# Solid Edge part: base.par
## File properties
Author: f_grande
Template: Normal.par
Last saved by: f_grande
Revision: 2
Application: Solid Edge
Material: Plexiglas opalino
Stile della faccia: Bianco (vetro)
Stile di riempimento: ANSI34(Plastica)
Stile virtuale: Marroncino (lucido)
Coef. of Thermal Exp: 0.0
Thermal Conductivity: 1.5
Specific Heat: 0.0
Modulus of Elasticity: 2757902.8
Poisson's Ratio: 0.4
Yield Stress: 6894757.0
Ultimate Stress: 0.0
Elongation: 0.0
Tipo di contenuto documento: 0
Densità: 1385,000 kg/m^3
Precisione: 0,990
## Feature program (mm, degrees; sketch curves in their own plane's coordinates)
sketch for "unnamed Protrusion 1" plane through (0, 0, 0) normal (0, 0, 1) x-axis (1, 0, 0)
  line (-24.5, 24.5) -> (24.5, 24.5)
  line (24.5, 24.5) -> (24.5, -24.5)
  line (24.5, -24.5) -> (-24.5, -24.5)
  line (-24.5, -24.5) -> (-24.5, 24.5)
  dimension (linear) = 24.5
  dimension (linear) = 24.5
extrude "unnamed Protrusion 1" add finite 1 along +normal
fillet "Rotondo_1" radius 3
sketch for "ExtrudedCutout_1" #1 plane through (0, 0, 1) normal (0, 0, 1) x-axis (1, 0, 0)
  circle centre (-24.5, 0) radius 2.5
sketch for "ExtrudedCutout_1" #2 plane through (0, 0, 1) normal (0, 0, 1) x-axis (1, 0, 0)
  circle centre (24.5, 0) radius 2.5
extrude "ExtrudedCutout_1" cut finite 135 along -normal
sketch for "ExtrudedCutout_2" plane through (0, 0, 1) normal (0, 0, 1) x-axis (1, 0, 0)
  line (-10.5, 24.5) -> (-10.5, 22.5)
  line (-10.5, 22.5) -> (-9.5, 22.5)
  line (-9.5, 22.5) -> (-9.5, 24.5)
  line (-9.5, 24.5) -> (-10.5, 24.5)
extrude "ExtrudedCutout_2" cut finite 135 along -normal
sketch for "ExtrudedCutout_3" plane through (0, 0, 1) normal (0, 0, 1) x-axis (1, 0, 0)
  line (9.5, 24.5) -> (9.5, 22.5)
  line (9.5, 22.5) -> (10.5, 22.5)
  line (10.5, 22.5) -> (10.5, 24.5)
  line (10.5, 24.5) -> (9.5, 24.5)
  dimension (linear) = 9.5
  dimension (linear) = 10.5
extrude "ExtrudedCutout_3" cut finite 135 along -normal
sketch for "ExtrudedCutout_4" #1 plane through (0, 0, 1) normal (0, 0, 1) x-axis (1, 0, 0)
  line (-9.5, -24.5) -> (-9.5, -22.5)
  line (-9.5, -22.5) -> (-10.5, -22.5)
  line (-10.5, -22.5) -> (-10.5, -24.5)
  line (-10.5, -24.5) -> (-9.5, -24.5)
sketch for "ExtrudedCutout_4" #2 plane through (0, 0, 1) normal (0, 0, 1) x-axis (1, 0, 0)
  line (10.5, -24.5) -> (10.5, -22.5)
  line (10.5, -22.5) -> (9.5, -22.5)
  line (9.5, -22.5) -> (9.5, -24.5)
  line (9.5, -24.5) -> (10.5, -24.5)
extrude "ExtrudedCutout_4" cut finite 135 along -normal
sketch for "ExtrudedCutout_5" #1 plane through (0, 0, 1) normal (0, 0, 1) x-axis (1, 0, 0)
  line (-24.5, -9.5) -> (-22.5, -9.5)
  line (-22.5, -9.5) -> (-22.5, -10.5)
  line (-22.5, -10.5) -> (-24.5, -10.5)
  line (-24.5, -10.5) -> (-24.5, -9.5)
sketch for "ExtrudedCutout_5" #2 plane through (0, 0, 1) normal (0, 0, 1) x-axis (1, 0, 0)
  line (24.5, 10.5) -> (22.5, 10.5)
  line (22.5, 10.5) -> (22.5, 9.5)
  line (22.5, 9.5) -> (24.5, 9.5)
  line (24.5, 9.5) -> (24.5, 10.5)
sketch for "ExtrudedCutout_5" #3 plane through (0, 0, 1) normal (0, 0, 1) x-axis (1, 0, 0)
  line (24.5, -10.5) -> (22.5, -10.5)
  line (22.5, -10.5) -> (22.5, -9.5)
  line (22.5, -9.5) -> (24.5, -9.5)
  line (24.5, -9.5) -> (24.5, -10.5)
sketch for "ExtrudedCutout_5" #4 plane through (0, 0, 1) normal (0, 0, 1) x-axis (1, 0, 0)
  line (-24.5, 10.5) -> (-24.5, 11.5)
  line (-24.5, 11.5) -> (-22.5, 11.5)
  line (-22.5, 11.5) -> (-22.5, 10.5)
  line (-22.5, 10.5) -> (-24.5, 10.5)
  dimension (linear) = 22.5
  dimension (linear) = 24.5
  dimension (linear) = 22.5
  dimension (linear) = 24.5
  dimension (linear) = 24.5
  dimension (linear) = 22.5
extrude "ExtrudedCutout_5" cut finite 135 along -normal
sketch for "ExtrudedCutout_6" plane through (0, 0, 1) normal (0, 0, 1) x-axis (1, 0, 0)
  line (-2, 24.5) -> (2, 24.5)
  line (2, 24.5) -> (2, 22.5)
  line (2, 22.5) -> (-2, 22.5)
  line (-2, 22.5) -> (-2, 24.5)
  dimension (linear) = 2
  dimension (linear) = 2
extrude "ExtrudedCutout_6" cut finite 135 along -normal
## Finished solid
Body 1: solid body, 50 faces, 144 edges, 96 vertices.
  Faces by surface: plane 44, cylinder 6
  Edges by curve: line 132, circle 12
Bounding box of the edges (mm): 49.000 x 49.000 x 1.000, from (-24.5, -24.5, 0) to (24.5, 24.5, 1).
Cylindrical faces by radius (mm): R2.5 x2, R3 x4
Planar faces by outward normal: +x 11, +y 11, +z 1, -x 11, -y 9, -z 1
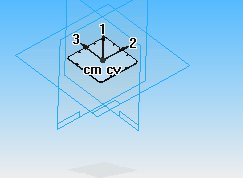
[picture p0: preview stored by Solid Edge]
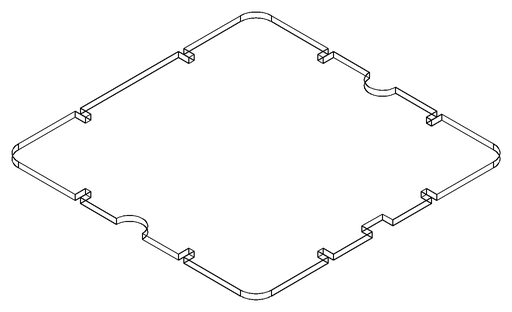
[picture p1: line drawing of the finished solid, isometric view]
